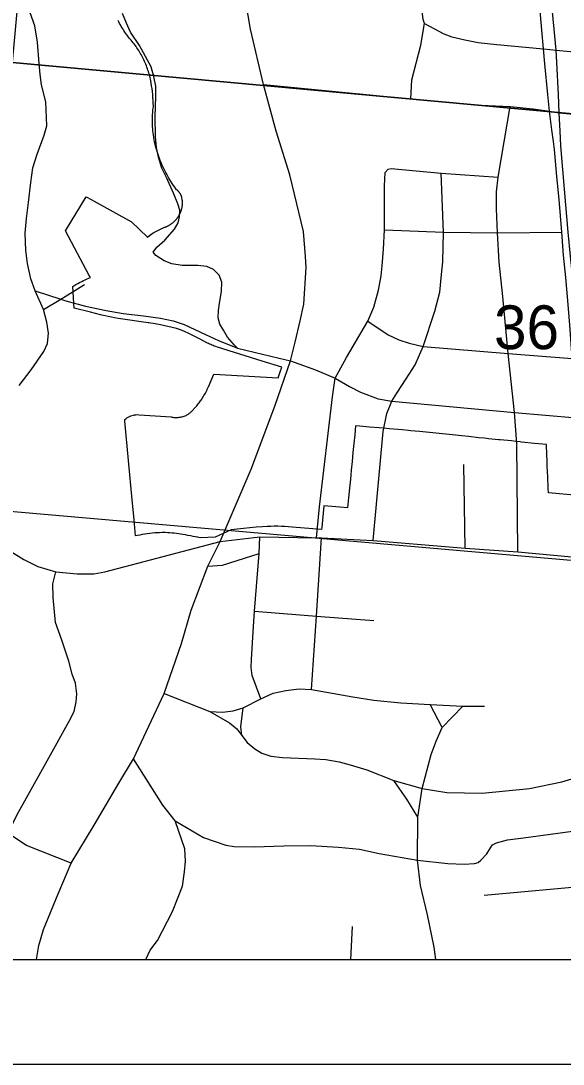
# Model space of a CAD drawing. Extents: x 0 to 34, y 0 to 22.
# Drawn here: x 6.822 to 7.342, y 14 to 14.998 of the extents above; entities that cross this region are included whole.
import ezdxf

# ---------------------------------------------------------------- set-up
doc = ezdxf.new("R2010")
doc.units = 0
for name, color, linetype in [('Default', 7, 'Continuous'), ('GM_X_City_Street', 7, 'Continuous'), ('GM_X_Corporation', 7, 'Continuous'), ('GM_X_Section', 7, 'Continuous'), ('GM_X_Section_Text', 7, 'Continuous'), ('GM_X_State_Route', 7, 'Continuous'), ('GM_X_Township_Road', 7, 'Continuous'), ('SH_Data', 7, 'Continuous')]:
    doc.layers.add(name, color=color, linetype=linetype)

msp = doc.modelspace()

# ---------------------------------------------------------------- linework, layer by layer
at = {"layer": 'Default'}
msp.add_lwpolyline([(6.72325, 14.1), (7.77344, 14.1), (7.79825, 14.44254), (6.76074, 14.53281), (6.76045, 14.51691)], close=True, dxfattribs=at)
at = {"layer": 'GM_X_City_Street'}
for p, q in [((7.27938, 14.84818), (7.29077, 14.91576)), ((7.15983, 14.50073), (7.16932, 14.60488)), ((7.29805, 14.48994), (7.29707, 14.59361)), ((7.24783, 14.4934), (7.24638, 14.57349)), ((7.10536, 14.50327), (7.10839, 14.5329)), ((7.22585, 14.32202), (7.24559, 14.34216)), ((7.26588, 14.16169), (7.39451, 14.17313)), ((7.13828, 14.1), (7.14004, 14.13157))]:
    msp.add_line(p, q, dxfattribs=at)
for points in [[(7.19563, 14.92294), (7.19685, 14.94116), (7.20527, 14.97439), (7.20886, 14.99514), (7.20761, 14.99903), (7.20371, 15.03039), (7.2009, 15.06845), (7.19965, 15.07906), (7.20059, 15.10309), (7.20153, 15.11479), (7.20371, 15.13023), (7.20605, 15.14349), (7.20776, 15.15582), (7.21142, 15.17373), (7.22038, 15.21037), (7.22742, 15.23272), (7.23428, 15.2569), (7.24448, 15.2888)], [(7.0132, 14.49983), (7.04304, 14.56885), (7.06561, 14.62916), (7.08051, 14.67263), (7.08519, 14.69039), (7.08992, 14.71079), (7.0935, 14.72667), (7.09557, 14.76166), (7.09509, 14.77239), (7.09289, 14.79629), (7.08009, 14.85042), (7.06692, 14.89211), (7.05473, 14.93674), (7.04217, 14.98978), (7.0304, 15.05913)], [(6.82097, 14.64882), (6.8323, 14.66398), (6.84454, 14.68151), (6.84805, 14.68922), (6.84901, 14.69909), (6.84746, 14.70964), (6.84428, 14.72145), (6.83622, 14.73932), (6.8322, 14.75083), (6.82874, 14.76544), (6.82728, 14.77822), (6.82654, 14.79466), (6.828, 14.80872), (6.82983, 14.82407), (6.8322, 14.84288), (6.83385, 14.85713), (6.83805, 14.8701), (6.84481, 14.88818), (6.84727, 14.89713), (6.84643, 14.92024), (6.84221, 14.93631), (6.8409, 14.94623), (6.83998, 14.95691), (6.8385, 14.97711), (6.83579, 14.99277), (6.8315, 15.00543)], [(7.02994, 14.68448), (7.02698, 14.68741), (7.02035, 14.69521), (7.01635, 14.70178), (7.01308, 14.70758), (7.01135, 14.71371), (7.01154, 14.72055), (7.01249, 14.72775), (7.01468, 14.73872), (7.01493, 14.74784), (7.01244, 14.75438), (7.00689, 14.75985), (7.00051, 14.76269), (6.9918, 14.76369), (6.97698, 14.76372), (6.96714, 14.76513), (6.95962, 14.768), (6.95178, 14.77316), (6.94921, 14.77628), (6.95275, 14.78112), (6.96015, 14.78777), (6.96956, 14.79853), (6.97314, 14.80452), (6.97443, 14.81019), (6.97461, 14.81665), (6.97287, 14.82279), (6.96858, 14.83279), (6.96177, 14.84782), (6.95745, 14.85668), (6.95432, 14.86741), (6.95229, 14.8766), (6.95142, 14.88689), (6.95118, 14.90591), (6.9517, 14.9253), (6.95159, 14.93519), (6.94993, 14.94436), (6.94714, 14.95357), (6.94171, 14.9636), (6.93592, 14.97403), (6.92751, 14.98682), (6.92357, 14.99529), (6.91964, 15.00452)], [(7.20886, 14.99514), (7.22749, 14.98532), (7.23505, 14.98234), (7.24728, 14.97935), (7.26021, 14.97677), (7.27822, 14.97488), (7.32281, 14.97074), (7.33473, 14.96963)], [(7.33473, 14.96963), (7.45437, 14.95858), (7.58146, 14.94729), (7.70421, 14.93624), (7.83323, 14.92441), (7.86384, 14.92148)], [(7.05473, 14.93674), (7.19563, 14.92294), (7.26282, 14.91698), (7.29077, 14.91576), (7.31281, 14.91355), (7.32855, 14.91135), (7.33779, 14.90977)], [(7.33779, 14.90977), (7.44885, 14.89925), (7.57526, 14.88819), (7.69868, 14.8765), (7.82851, 14.86492)], [(7.17112, 14.85258), (7.174, 14.85565), (7.17696, 14.85642), (7.22489, 14.85192), (7.27938, 14.84818)], [(7.10839, 14.5329), (7.12092, 14.63818), (7.12338, 14.65579), (7.13432, 14.67555), (7.15465, 14.71039), (7.16022, 14.72386), (7.16478, 14.73993), (7.16744, 14.75393), (7.16846, 14.76341), (7.16965, 14.77935), (7.17065, 14.79781), (7.17065, 14.83942), (7.17112, 14.85258)], [(7.16932, 14.60488), (7.17294, 14.6223), (7.17764, 14.6339), (7.18233, 14.64155), (7.19122, 14.65531), (7.19985, 14.66873), (7.20092, 14.67086), (7.20744, 14.68631), (7.21887, 14.72012), (7.22362, 14.73803), (7.22523, 14.75501), (7.22631, 14.76715), (7.22713, 14.7955), (7.22489, 14.85192)], [(7.29707, 14.59361), (7.29483, 14.62324), (7.28905, 14.67941), (7.28376, 14.73417), (7.28025, 14.76681), (7.27883, 14.79497), (7.27782, 14.81784), (7.27784, 14.834), (7.27938, 14.84818)], [(7.17065, 14.79781), (7.22713, 14.7955), (7.27883, 14.79497), (7.34032, 14.7954)], [(6.84428, 14.72145), (6.86064, 14.73156), (6.88355, 14.74535)], [(6.83622, 14.73932), (6.86064, 14.73156), (6.86566, 14.72984)], [(6.86566, 14.72984), (6.88439, 14.72488), (6.90401, 14.72061), (6.92036, 14.71778), (6.93983, 14.71549), (6.95604, 14.71336), (6.96841, 14.71067), (6.97879, 14.70711), (6.99926, 14.69772), (7.01163, 14.69189), (7.02994, 14.68448), (7.0696, 14.67518)], [(7.15465, 14.71039), (7.17396, 14.69747), (7.18437, 14.69271), (7.19427, 14.68932), (7.20744, 14.68631), (7.28905, 14.67941), (7.35032, 14.67462), (7.35688, 14.67411)], [(7.0696, 14.67518), (7.08051, 14.67263), (7.10461, 14.66403), (7.12338, 14.65579), (7.13702, 14.64782), (7.14746, 14.64269), (7.16434, 14.63613), (7.17764, 14.6339), (7.29483, 14.62324), (7.35419, 14.61804)], [(6.28784, 14.66728), (6.34893, 14.6487), (6.45161, 14.61893), (6.52667, 14.59923), (6.6213, 14.57436), (6.68486, 14.55652), (6.71161, 14.54761), (6.73821, 14.53567), (6.77373, 14.51453), (6.8255, 14.48246), (6.83873, 14.47599), (6.85613, 14.47081), (6.87641, 14.4688), (6.89223, 14.46894), (6.90273, 14.47081), (6.94645, 14.48218), (7.0132, 14.49983), (7.05128, 14.50431), (7.10536, 14.50327), (7.11039, 14.50312), (7.15983, 14.50073), (7.24783, 14.4934), (7.29805, 14.48994), (7.36696, 14.48349)], [(6.94209, 14.1), (6.94622, 14.10886), (6.95336, 14.11822), (6.96759, 14.14587), (6.97713, 14.17019), (6.97914, 14.1839), (6.98024, 14.19398), (6.97933, 14.20574), (6.97034, 14.2325), (6.95836, 14.24748), (6.9304, 14.29202), (6.95974, 14.35435), (6.97616, 14.40227), (6.98552, 14.43423), (7.00157, 14.47627), (7.0132, 14.49983)], [(7.04325, 14.38698), (7.04477, 14.41332), (7.04617, 14.43307), (7.05072, 14.48836), (7.05128, 14.50431)], [(7.1006, 14.35819), (7.10534, 14.42843), (7.11039, 14.50312)], [(7.00157, 14.47627), (7.01548, 14.47697), (7.05072, 14.48836)], [(6.80835, 14.21461), (6.80852, 14.21655), (6.81005, 14.221), (6.8201, 14.24101), (6.84755, 14.28994), (6.86884, 14.32803), (6.87351, 14.33718), (6.87538, 14.34652), (6.87593, 14.35417), (6.87482, 14.36426), (6.87176, 14.37298), (6.86847, 14.38536), (6.86164, 14.40546), (6.85558, 14.42215), (6.85334, 14.44624), (6.85316, 14.4593), (6.85613, 14.47081)], [(7.04617, 14.43307), (7.10534, 14.42843), (7.16023, 14.42412)], [(6.87065, 14.19229), (6.82807, 14.20898), (6.81005, 14.221), (6.79712, 14.23693), (6.78736, 14.254), (6.78062, 14.26751), (6.76098, 14.30194), (6.75109, 14.32048), (6.74497, 14.33484), (6.73897, 14.34385), (6.72866, 14.35416), (6.71937, 14.35998), (6.71093, 14.36279), (6.69977, 14.36551), (6.6918, 14.36832), (6.68476, 14.37151), (6.67943, 14.37658), (6.66736, 14.39957)], [(7.05232, 14.34919), (7.04382, 14.37173), (7.0428, 14.37917), (7.04325, 14.38698)], [(7.00345, 14.33709), (7.01538, 14.33643), (7.02584, 14.33782), (7.03533, 14.34057), (7.05232, 14.34919), (7.06394, 14.35463), (7.07622, 14.35735), (7.08898, 14.35885), (7.1006, 14.35819), (7.14009, 14.35116), (7.16025, 14.34816), (7.18604, 14.34544), (7.21438, 14.3438), (7.24559, 14.34216), (7.26642, 14.34235)], [(6.95974, 14.35435), (7.00345, 14.33709), (7.0222, 14.32622), (7.02923, 14.32059), (7.0341, 14.31415), (7.03917, 14.30746), (7.0463, 14.30146), (7.05324, 14.29733), (7.06169, 14.29433), (7.07303, 14.29321), (7.10388, 14.29208), (7.11448, 14.29133), (7.12705, 14.28899), (7.13774, 14.28617), (7.15369, 14.28157), (7.17936, 14.2713), (7.20653, 14.26364), (7.23012, 14.25982), (7.26407, 14.25907), (7.30927, 14.26357), (7.34022, 14.26995), (7.36254, 14.27651), (7.3839, 14.2808)], [(7.0341, 14.31415), (7.03308, 14.32247), (7.03533, 14.34057)], [(7.21965, 14.1), (7.21812, 14.11169), (7.2118, 14.1428), (7.20494, 14.17079), (7.20224, 14.19501), (7.20236, 14.23618), (7.20653, 14.26364), (7.2153, 14.29602), (7.22005, 14.30867), (7.22585, 14.32202), (7.21438, 14.3438)], [(6.8374, 14.1), (6.83985, 14.11338), (6.84429, 14.1288), (6.85836, 14.16294), (6.87065, 14.19229), (6.89269, 14.22859), (6.91632, 14.26872), (6.9304, 14.29202)], [(7.20236, 14.23618), (7.19182, 14.25349), (7.17936, 14.2713)], [(6.97034, 14.2325), (6.99724, 14.21666), (7.01866, 14.20941), (7.0267, 14.20815), (7.04583, 14.20784), (7.0741, 14.20862), (7.09969, 14.20902), (7.12662, 14.20752), (7.14662, 14.20571), (7.16559, 14.20146), (7.20224, 14.19501), (7.23115, 14.19182), (7.24672, 14.19117), (7.25666, 14.19201), (7.26023, 14.19276), (7.26276, 14.19492), (7.26848, 14.20111), (7.27185, 14.20683), (7.27401, 14.20964), (7.27786, 14.21152), (7.28836, 14.21443), (7.30356, 14.21649), (7.39034, 14.22813)]]:
    msp.add_lwpolyline(points, dxfattribs=at)
at = {"layer": 'GM_X_Corporation'}
msp.add_lwpolyline([(7.35196, 14.54403), (7.3275, 14.54634), (7.32731, 14.55073), (7.32684, 14.56157), (7.32639, 14.57187), (7.32615, 14.57743), (7.32594, 14.58217), (7.32549, 14.59244), (7.31403, 14.59361), (7.30158, 14.59488), (7.3003, 14.59501), (7.29633, 14.59543), (7.29201, 14.59589), (7.2812, 14.59695), (7.27951, 14.59712), (7.27009, 14.59808), (7.26638, 14.59846), (7.26067, 14.59904), (7.25125, 14.60001), (7.24459, 14.60069), (7.24183, 14.60097), (7.23241, 14.60193), (7.22298, 14.6029), (7.2228, 14.60292), (7.21356, 14.60386), (7.20414, 14.60482), (7.19585, 14.60567), (7.19361, 14.6059), (7.1874, 14.60645), (7.17493, 14.60755), (7.17017, 14.60797), (7.16549, 14.60839), (7.15605, 14.60922), (7.14661, 14.61006), (7.14284, 14.61039), (7.142, 14.6018), (7.14118, 14.59332), (7.14063, 14.58767), (7.14036, 14.58484), (7.13953, 14.57636), (7.13871, 14.56787), (7.1383, 14.56363), (7.13788, 14.55939), (7.13705, 14.55086), (7.13614, 14.54143), (7.13522, 14.53201), (7.12767, 14.53264), (7.12012, 14.53328), (7.11257, 14.53391), (7.11056, 14.5132), (7.11037, 14.51123), (7.10584, 14.51161), (7.10203, 14.51193), (7.08214, 14.5136), (7.07872, 14.51386), (7.07531, 14.51406), (7.07189, 14.51419), (7.06847, 14.51427), (7.06505, 14.51429), (7.06163, 14.51425), (7.05821, 14.51415), (7.05373, 14.51392), (7.04768, 14.5135), (7.04164, 14.51297), (7.03561, 14.51233), (7.0268, 14.51118), (7.02382, 14.51078), (7.00837, 14.50384), (6.99406, 14.50335), (6.99161, 14.50381), (6.99098, 14.50393), (6.98961, 14.50418), (6.98734, 14.50461), (6.98508, 14.50503), (6.98235, 14.50554), (6.98008, 14.50597), (6.97759, 14.50643), (6.97529, 14.50684), (6.97335, 14.50714), (6.97148, 14.50739), (6.96937, 14.50764), (6.96728, 14.50784), (6.96502, 14.50802), (6.96309, 14.50812), (6.96053, 14.50821), (6.95772, 14.50824), (6.95506, 14.5082), (6.95268, 14.5081), (6.95062, 14.50798), (6.94811, 14.50777), (6.94592, 14.50754), (6.94334, 14.50721), (6.94115, 14.50688), (6.93858, 14.50643), (6.93623, 14.50596), (6.93418, 14.50551), (6.93233, 14.50506), (6.93086, 14.52033), (6.93081, 14.52083), (6.92907, 14.53946), (6.92204, 14.6149), (6.9219, 14.61638), (6.92285, 14.61716), (6.92401, 14.61798), (6.92526, 14.61873), (6.92657, 14.61938), (6.92769, 14.61984), (6.92905, 14.62029), (6.93024, 14.6206), (6.93134, 14.62081), (6.9325, 14.62096), (6.93427, 14.62105), (6.93561, 14.621), (6.96634, 14.61884), (6.96715, 14.61868), (6.96788, 14.61856), (6.96872, 14.61846), (6.96944, 14.61839), (6.97022, 14.61834), (6.97111, 14.61832), (6.97207, 14.61834), (6.97306, 14.6184), (6.97404, 14.6185), (6.97492, 14.61863), (6.97592, 14.61882), (6.97691, 14.61905), (6.97785, 14.61932), (6.97882, 14.61964), (6.97968, 14.61996), (6.98059, 14.62035), (6.98141, 14.62075), (6.98228, 14.62121), (6.98299, 14.62162), (6.98312, 14.62173), (6.98353, 14.62209), (6.98395, 14.62246), (6.98445, 14.62291), (6.98487, 14.62329), (6.98549, 14.62387), (6.98607, 14.62442), (6.98696, 14.6253), (6.98766, 14.62601), (6.98822, 14.6266), (6.98914, 14.62758), (6.98996, 14.62849), (6.99083, 14.6295), (6.99167, 14.63052), (6.99232, 14.63133), (6.99307, 14.63228), (6.99377, 14.63321), (6.99446, 14.63416), (6.99507, 14.63504), (6.99572, 14.63599), (6.99642, 14.63706), (6.99706, 14.63808), (6.99776, 14.63924), (6.99848, 14.64048), (6.9991, 14.64161), (6.99979, 14.64292), (7.00003, 14.64339), (7.00036, 14.64405), (7.00069, 14.64473), (7.00096, 14.6453), (7.00125, 14.64593), (7.00153, 14.64657), (7.0018, 14.64718), (7.00196, 14.64756), (7.00725, 14.65961), (7.00731, 14.65961), (7.06873, 14.65625), (7.06885, 14.65625), (7.07061, 14.66184), (7.07215, 14.66642), (7.0535, 14.67225), (7.01077, 14.68559), (7.00898, 14.68618), (7.00755, 14.68669), (7.00652, 14.68709), (7.00534, 14.68757), (7.00428, 14.68802), (7.00304, 14.68858), (7.00202, 14.68907), (7.00106, 14.68956), (6.99344, 14.69346), (6.98385, 14.69836), (6.97847, 14.70087), (6.97449, 14.70243), (6.97155, 14.70343), (6.95615, 14.70701), (6.95099, 14.70793), (6.94515, 14.70879), (6.94444, 14.70889), (6.91563, 14.71312), (6.91222, 14.71365), (6.90915, 14.71419), (6.90609, 14.71478), (6.90305, 14.71543), (6.90001, 14.71612), (6.89878, 14.71644), (6.88903, 14.71894), (6.87357, 14.72291), (6.87351, 14.72294), (6.87326, 14.72745), (6.87236, 14.7437), (6.87236, 14.74372), (6.87337, 14.74438), (6.8751, 14.74545), (6.87697, 14.74653), (6.87868, 14.74747), (6.88074, 14.74852), (6.88243, 14.74932), (6.88415, 14.75009), (6.88587, 14.75082), (6.88768, 14.75152), (6.88916, 14.75206), (6.88798, 14.75425), (6.86511, 14.79697), (6.88487, 14.82944), (6.88989, 14.82667), (6.92856, 14.8053), (6.94371, 14.79063), (6.94723, 14.79355), (6.94746, 14.79374), (6.9492, 14.79481), (6.95043, 14.79552), (6.95167, 14.79622), (6.95293, 14.79689), (6.95419, 14.79754), (6.95546, 14.79817), (6.95675, 14.79877), (6.95805, 14.79935), (6.95935, 14.79992), (6.95979, 14.80006), (6.96023, 14.80022), (6.96066, 14.80038), (6.96109, 14.80055), (6.96152, 14.80073), (6.96194, 14.80092), (6.96236, 14.80111), (6.96278, 14.80131), (6.96319, 14.80152), (6.9636, 14.80173), (6.96401, 14.80195), (6.96441, 14.80218), (6.96481, 14.80242), (6.9652, 14.80266), (6.96559, 14.80291), (6.96598, 14.80317), (6.96636, 14.80343), (6.96673, 14.8037), (6.96711, 14.80398), (6.96747, 14.80426), (6.96783, 14.80455), (6.96819, 14.80484), (6.96854, 14.80514), (6.96889, 14.80545), (6.96923, 14.80577), (6.96956, 14.80609), (6.96989, 14.80641), (6.97021, 14.80674), (6.97053, 14.80708), (6.97084, 14.80742), (6.97115, 14.80777), (6.97145, 14.80812), (6.97174, 14.80848), (6.97203, 14.80884), (6.97231, 14.80921), (6.97259, 14.80958), (6.97285, 14.80996), (6.97311, 14.81034), (6.97337, 14.81073), (6.97376, 14.81135), (6.97397, 14.81171), (6.97418, 14.81206), (6.97437, 14.81243), (6.97457, 14.81279), (6.97475, 14.81316), (6.97493, 14.81353), (6.97511, 14.81391), (6.97527, 14.81429), (6.97543, 14.81467), (6.97559, 14.81505), (6.97573, 14.81544), (6.97587, 14.81583), (6.976, 14.81622), (6.97613, 14.81661), (6.97625, 14.81701), (6.97636, 14.8174), (6.97647, 14.8178), (6.97657, 14.8182), (6.97666, 14.81861), (6.97674, 14.81901), (6.97682, 14.81942), (6.97689, 14.81983), (6.97695, 14.82023), (6.97701, 14.82064), (6.97706, 14.82105), (6.9771, 14.82146), (6.97713, 14.82188), (6.97716, 14.82229), (6.97718, 14.8227), (6.97719, 14.82311), (6.9772, 14.82353), (6.9772, 14.82394), (6.97719, 14.82435), (6.97717, 14.82477), (6.97712, 14.82558), (6.97704, 14.82651), (6.97672, 14.82848), (6.97652, 14.82918), (6.97651, 14.82924), (6.9765, 14.82927), (6.97645, 14.82944), (6.97641, 14.82962), (6.97639, 14.8297), (6.97635, 14.82988), (6.97629, 14.83014), (6.97612, 14.83034), (6.97601, 14.83058), (6.9759, 14.83082), (6.97578, 14.83106), (6.97566, 14.83129), (6.97554, 14.83152), (6.97541, 14.83175), (6.97528, 14.83198), (6.97515, 14.8322), (6.97501, 14.83243), (6.97487, 14.83265), (6.97472, 14.83286), (6.97457, 14.83308), (6.97442, 14.83329), (6.97426, 14.8335), (6.9741, 14.83371), (6.97393, 14.83391), (6.97376, 14.83411), (6.97359, 14.83431), (6.97341, 14.8345), (6.97324, 14.83469), (6.97305, 14.83488), (6.97287, 14.83507), (6.97268, 14.83525), (6.97249, 14.83543), (6.97229, 14.83561), (6.9721, 14.83578), (6.97205, 14.83581), (6.97189, 14.83595), (6.97162, 14.83617), (6.96982, 14.83862), (6.96863, 14.84031), (6.96747, 14.84203), (6.96634, 14.84377), (6.96524, 14.84553), (6.96417, 14.8473), (6.96313, 14.8491), (6.96212, 14.85091), (6.96114, 14.85274), (6.9602, 14.85458), (6.95929, 14.85645), (6.95841, 14.85833), (6.95757, 14.86022), (6.95675, 14.86213), (6.95598, 14.86405), (6.95523, 14.86598), (6.95452, 14.86793), (6.95384, 14.86989), (6.9532, 14.87186), (6.95259, 14.87384), (6.95202, 14.87584), (6.95148, 14.87784), (6.95097, 14.87985), (6.95051, 14.88187), (6.95007, 14.8839), (6.94968, 14.88593), (6.94931, 14.88866), (6.94909, 14.8906), (6.94891, 14.89254), (6.94876, 14.89449), (6.94864, 14.89644), (6.94856, 14.89839), (6.94851, 14.90034), (6.94849, 14.9023), (6.94851, 14.90425), (6.94857, 14.9062), (6.94865, 14.90815), (6.94878, 14.9101), (6.94893, 14.91205), (6.94912, 14.914), (6.94935, 14.91594), (6.94925, 14.91875), (6.94911, 14.92157), (6.94891, 14.92438), (6.94867, 14.92719), (6.94838, 14.92999), (6.94804, 14.93279), (6.94765, 14.93558), (6.94687, 14.94034), (6.94656, 14.9418), (6.94623, 14.94326), (6.94587, 14.94472), (6.94549, 14.94617), (6.94508, 14.94761), (6.94465, 14.94904), (6.94419, 14.95047), (6.94371, 14.95188), (6.94321, 14.95329), (6.94268, 14.95469), (6.94212, 14.95608), (6.94154, 14.95746), (6.94094, 14.95883), (6.94031, 14.96019), (6.93966, 14.96154), (6.93898, 14.96288), (6.93829, 14.9642), (6.93757, 14.96551), (6.93682, 14.96681), (6.93606, 14.9681), (6.93527, 14.96937), (6.93446, 14.97063), (6.93363, 14.97187), (6.93277, 14.9731), (6.9319, 14.97432), (6.931, 14.97552), (6.93008, 14.9767), (6.92915, 14.97787), (6.92819, 14.97902), (6.9263, 14.98118), (6.92486, 14.98302), (6.9239, 14.98431), (6.92296, 14.98561), (6.92205, 14.98693), (6.92116, 14.98826), (6.92029, 14.98961), (6.91945, 14.99098), (6.91863, 14.99236), (6.91783, 14.99375), (6.91706, 14.99516), (6.91632, 14.99658), (6.9156, 14.99801)], dxfattribs=at)
at = {"layer": 'GM_X_Section'}
for points in [[(6.90635, 15.9571), (7.90346, 15.87364), (7.82775, 14.86502), (6.81453, 14.95787)], [(6.79602, 14.96048), (6.81453, 14.95787), (7.82775, 14.86502), (7.79825, 14.44254), (6.76074, 14.53281)]]:
    msp.add_lwpolyline(points, close=True, dxfattribs=at)
at = {"layer": 'GM_X_State_Route'}
for points in [[(7.3323, 14.88211), (7.33086, 14.89354), (7.32855, 14.91135), (7.3268, 14.92718), (7.32409, 14.9564), (7.32281, 14.97074), (7.32117, 14.98868), (7.31846, 15.01831)], [(7.33927, 14.87854), (7.33853, 14.89204), (7.33779, 14.90977), (7.33718, 14.92703), (7.33546, 14.9577), (7.33473, 14.96963), (7.33291, 14.98978), (7.33015, 15.01947)], [(7.35919, 14.53675), (7.35794, 14.55787), (7.35652, 14.58408), (7.35528, 14.60252), (7.35419, 14.61804), (7.35283, 14.63814), (7.35195, 14.65038), (7.35032, 14.67462), (7.3488, 14.69344), (7.34802, 14.7065), (7.34656, 14.72261), (7.34395, 14.75224), (7.34203, 14.77369), (7.34032, 14.7954), (7.33758, 14.82668), (7.3356, 14.84881), (7.33325, 14.87448), (7.3323, 14.88211)], [(7.36723, 14.55458), (7.36716, 14.5556), (7.36498, 14.58406), (7.36341, 14.60267), (7.36206, 14.61725), (7.36013, 14.63788), (7.35905, 14.65061), (7.35688, 14.67411), (7.35531, 14.69551), (7.35464, 14.70645), (7.35349, 14.72129), (7.35068, 14.75139), (7.34854, 14.77272), (7.34625, 14.79544), (7.34276, 14.83673), (7.3395, 14.87439), (7.33927, 14.87854)]]:
    msp.add_lwpolyline(points, dxfattribs=at)
at = {"layer": 'GM_X_Township_Road'}
msp.add_lwpolyline([(3.92512, 14.1), (8.9, 14.1), (8.9, 20.9)], dxfattribs=at)
at = {"layer": 'SH_Data'}
for p, q in [((2.1, 14.1), (8.9, 14.1)), ((2, 14), (9, 14))]:
    msp.add_line(p, q, dxfattribs=at)

# ---------------------------------------------------------------- texts
at = {"layer": 'GM_X_Section_Text'}
msp.add_text('36', height=0.041856, rotation=0.00001, dxfattribs=at).set_placement((7.27535, 14.68367))

doc.saveas('drawing.dxf')
